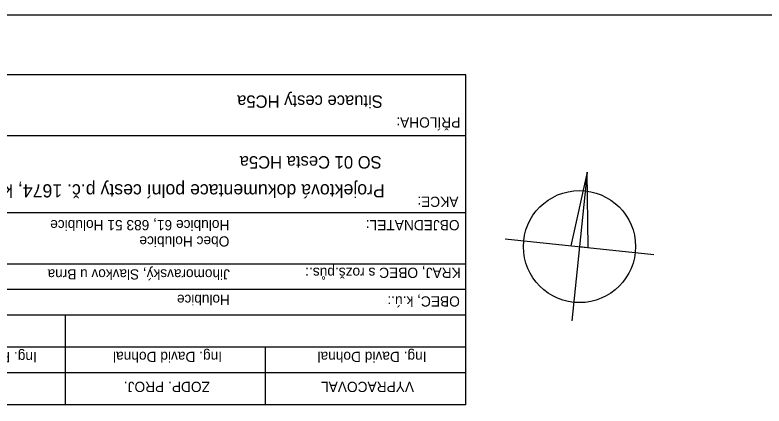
# Model space of a CAD drawing. Extents: x -583470 to -583050, y -1165714 to -1165417.
# Drawn here: x -583385.2 to -583260.4, y -1165482.5 to -1165417.3 of the extents above; entities that cross this region are included whole.
import ezdxf

# ---------------------------------------------------------------- set-up
doc = ezdxf.new("R2010")
doc.units = 0
doc.layers.add('Ram PR2a', color=7, linetype='Continuous')

msp = doc.modelspace()

# ---------------------------------------------------------------- linework, layer by layer
for p, q in [((-583310.1, -1165427.31), (-583460.1, -1165427.31)), ((-583310.1, -1165482.31), (-583310.1, -1165427.31)), ((-583310.1, -1165437.45), (-583460.1, -1165437.45)), ((-583410.1, -1165458.82), (-583310.1, -1165458.82)), ((-583310.1, -1165463.09), (-583410.1, -1165463.09)), ((-583310.1, -1165467.36), (-583410.1, -1165467.36)), ((-583376.76, -1165482.31), (-583376.76, -1165467.31)), ((-583310.1, -1165472.7), (-583410.1, -1165472.7)), ((-583343.43, -1165482.31), (-583343.43, -1165472.7)), ((-583310.1, -1165476.97), (-583410.1, -1165476.97)), ((-583310.1, -1165482.31), (-583460.1, -1165482.31))]:
    msp.add_line(p, q)
msp.add_lwpolyline([(-583050.1, -1165714.31), (-583470.1, -1165714.31), (-583470.1, -1165417.31), (-583050.1, -1165417.31)], close=True)
msp.add_lwpolyline([(-583410.1, -1165450.27), (-583310.1, -1165450.27)])
at = {"layer": 'Ram PR2a'}
for p, q in [((-583289.85, -1165443.54), (-583292.58, -1165455.78)), ((-583289.85, -1165443.54), (-583292.45, -1165468.32)), ((-583303.54, -1165454.63), (-583278.76, -1165457.23))]:
    msp.add_line(p, q, dxfattribs=at)
msp.add_lwpolyline([(-583289.85, -1165443.54), (-583291.15, -1165455.93), (-583289.73, -1165456.08)], close=True, dxfattribs=at)
msp.add_circle((-583291.15, -1165455.93), 9.34, dxfattribs=at)

# ---------------------------------------------------------------- texts
for s, height, p in [('Situace cesty HC5a', 2.0663, (-583323.91, -1165430.72)), ('PŘÍLOHA:', 1.709, (-583311, -1165434.38)), ('SO 01 Cesta HC5a', 2.0663, (-583324.1, -1165440.85)), ('Projektová dokumentace polní cesty p.č. 1674, k.ú. Holubice', 2.2043, (-583323.58, -1165445.53)), ('AKCE:', 1.709, (-583311.31, -1165447.6)), ('Holubice 61, 683 51 Holubice', 1.7089, (-583349.47, -1165451.5)), ('OBJEDNATEL:', 1.7089, (-583311.13, -1165451.5)), ('Obec Holubice', 1.7089, (-583349.47, -1165454.21)), ('Jihomoravský, Slavkov u Brna', 1.6953, (-583349.39, -1165459.71)), ('KRAJ, OBEC s rozš.půs.:', 1.7089, (-583310.93, -1165459.44)), ('Holubice', 1.695, (-583349.39, -1165463.95)), ('OBEC, k.ú.:', 1.7089, (-583311.08, -1165464.21)), ('Ing. František Hanousek', 1.7089, (-583381.55, -1165473.51)), ('Ing. David Dohnal', 1.7089, (-583350.69, -1165473.46)), ('Ing. David Dohnal', 1.7089, (-583316.63, -1165473.46)), ('ZODP. PROJ.', 1.7089, (-583352.71, -1165478.46)), ('VYPRACOVAL', 1.709, (-583318.71, -1165478.46))]:
    msp.add_text(s, height=height, rotation=180).set_placement(p)

doc.saveas('drawing.dxf')
